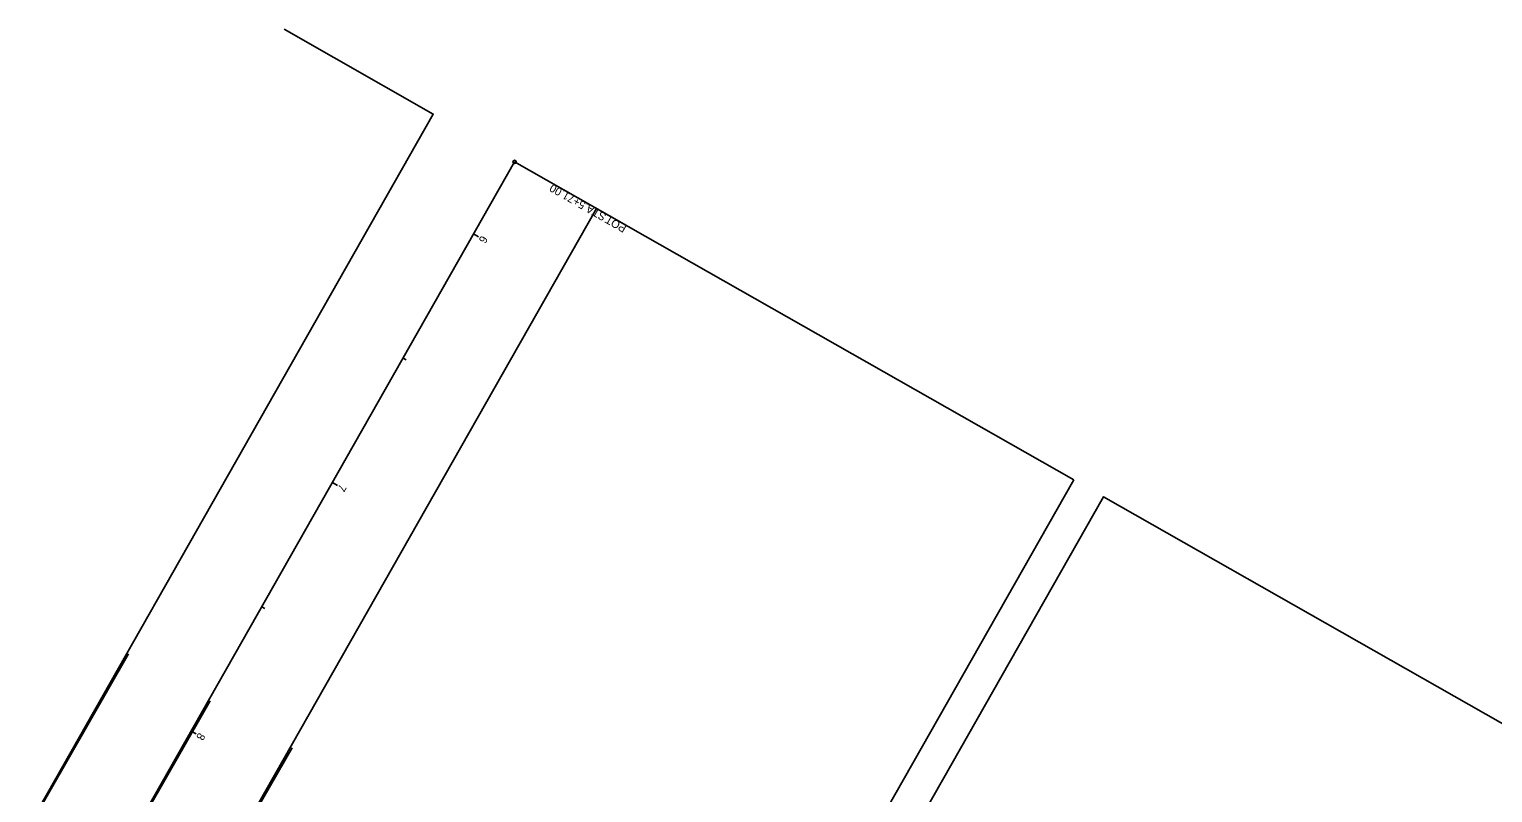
# Model space of a CAD drawing. Extents: x 119320 to 120701, y 385020 to 386199.
# Drawn here: x 119728 to 120240, y 385932 to 386199 of the extents above; entities that cross this region are included whole.
import ezdxf

# ---------------------------------------------------------------- set-up
doc = ezdxf.new("R2010")
doc.units = 0
for name, color, linetype in [('RW_X_CL', 7, 'Continuous'), ('RW_X_CL_100_Cardinal_Points', 7, 'Continuous'), ('RW_X_CL_100_Stations', 7, 'Continuous'), ('RW_X_Fee_RW', 7, 'Continuous'), ('SC_Scratch1', 7, 'Continuous')]:
    doc.layers.add(name, color=color, linetype=linetype)

msp = doc.modelspace()

# ---------------------------------------------------------------- linework, layer by layer
at = {"layer": 'RW_X_CL'}
msp.add_line((119897.55, 386152.97), (119478.5, 385415.75), dxfattribs=at)
at = {"layer": 'RW_X_CL_100_Cardinal_Points'}
msp.add_line((119897.55, 386152.97), (119936.68, 386130.73), dxfattribs=at)
msp.add_circle((119897.55, 386152.97), 0.6, dxfattribs=at)
at = {"layer": 'RW_X_CL_100_Stations'}
for p, q in [((119883.22, 386127.76), (119884.96, 386126.77)), ((119858.52, 386084.29), (119859.56, 386083.7)), ((119833.81, 386040.82), (119835.55, 386039.84)), ((119809.1, 385997.36), (119810.14, 385996.76)), ((119784.39, 385953.89), (119786.13, 385952.9))]:
    msp.add_line(p, q, dxfattribs=at)
at = {"layer": 'RW_X_Fee_RW'}
msp.add_line((120093.16, 386041.78), (119926.24, 386136.66), dxfattribs=at)
for points in [[(119507.99, 385918.9), (119673.17, 385825.01), (119869.11, 386169.71), (119816.95, 386199.36)], [(119926.24, 386136.66), (119730.55, 385792.4), (119897.47, 385697.52), (120093.16, 386041.78)], [(119907.9, 385691.58), (120074.82, 385596.7), (120270.51, 385940.97), (120103.59, 386035.85), (119907.9, 385691.58)]]:
    msp.add_lwpolyline(points, dxfattribs=at)
at = {"layer": 'SC_Scratch1'}
for p, q in [((119530.56, 385576.63), (119762.43, 385980.86)), ((119559.19, 385560.21), (119791.06, 385964.44)), ((119730.86, 385793.18), (119819.68, 385948.02))]:
    msp.add_line(p, q, dxfattribs=at)

# ---------------------------------------------------------------- texts
at = {"layer": 'RW_X_CL_100_Cardinal_Points'}
for s, p in [('5+71.00', (119922.67, 386138.65)), (' STA. ', (119930.78, 386134.04)), ('POT', (119936.98, 386130.52))]:
    msp.add_text(s, height=2.8, rotation=150.3847, dxfattribs=at).set_placement(p)
at = {"layer": 'RW_X_CL_100_Stations'}
for s, p in [('6', (119885.9, 386127.41)), ('7', (119836.48, 386040.47)), ('8', (119787.06, 385953.53))]:
    msp.add_text(s, height=2.8, rotation=240.3847, dxfattribs=at).set_placement(p)

doc.saveas('drawing.dxf')
